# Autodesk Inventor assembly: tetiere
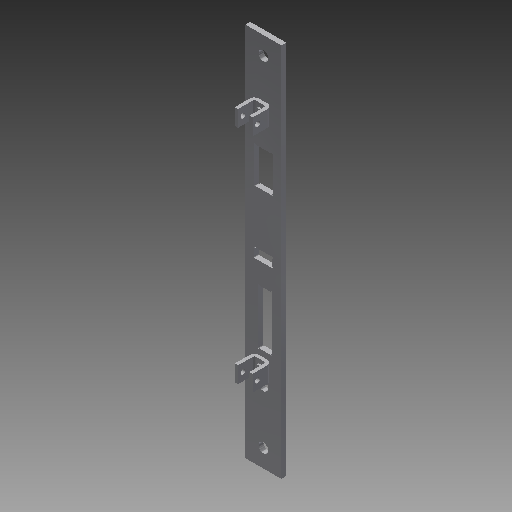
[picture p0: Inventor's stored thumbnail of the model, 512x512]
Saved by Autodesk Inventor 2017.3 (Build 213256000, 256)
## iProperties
Created: 2007-12
Part Number: tetiere
Material: Générique
Document SubType Name: Assembly
Designer: ficho
Author: ficho
Sending System: SolidWorks 2009
Last Author: christophe
Last Saved: 2011-02-10
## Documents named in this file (3)
- G:\travail\année 2019-2020\réforme\toussaint\Serrure biométrique SET\Documentations_pedagogique\Modelisation_Solidworks\tetiere.iam
- G:\travail\année 2019-2020\réforme\toussaint\Serrure biométrique SET\Documentations_pedagogique\Modelisation_Solidworks\tetiere.ipt
- G:\travail\année 2019-2020\réforme\toussaint\Serrure biométrique SET\Documentations_pedagogique\Modelisation_Solidworks\Pièce37.ipt
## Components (3 placed, 2 different names)
1. tetiere:1
2. Pièce37:1
3. Pièce37:2
